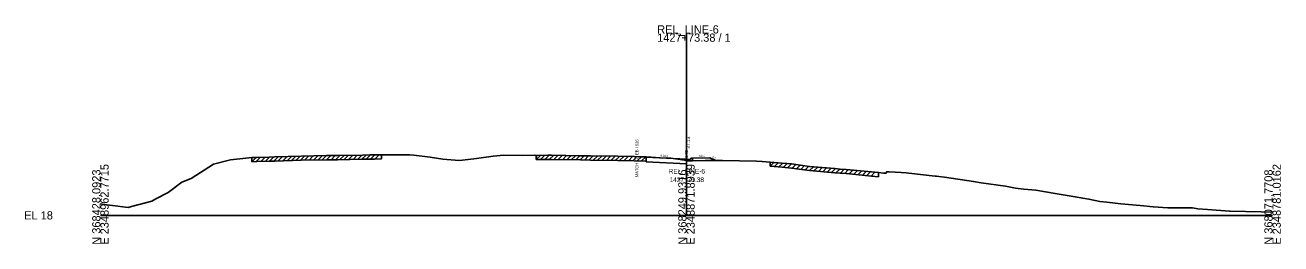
# Model space of a CAD drawing. Extents: x -26 to 403, y -10 to 6565.
# Drawn here: x -25.7 to 402.8, y 6490.3 to 6564.8 of the extents above; entities that cross this region are included whole.
import ezdxf

# ---------------------------------------------------------------- set-up
doc = ezdxf.new("R2010")
doc.units = 0
for name, color, linetype in [('RD_GPK_XS_Cell', 7, 'Continuous'), ('RD_XS_Base', 7, 'Continuous'), ('RD_XS_CurbBase', 7, 'Continuous'), ('RD_XS_CurbFront', 7, 'Continuous'), ('RD_XS_CurbTop', 7, 'Continuous'), ('RD_XS_EarthShd', 7, 'Continuous'), ('RD_XS_ExGround', 7, 'Continuous'), ('RD_XS_ExPaveRet', 7, 'Continuous'), ('RD_XS_Pave', 7, 'Continuous'), ('RD_XS_TieSlope', 7, 'Continuous'), ('RD_XS_TX_Elev_EX', 7, 'Continuous'), ('RD_XS_TX_Elev_PR', 7, 'Continuous'), ('RD_XS_TX_MatchLine', 7, 'Continuous'), ('RD_XS_TX_Slope', 7, 'Continuous'), ('RD_XS_TX_Station', 7, 'Continuous'), ('RD_XS_TX_TOC', 7, 'Continuous')]:
    doc.layers.add(name, color=color, linetype=linetype)

msp = doc.modelspace()

# ---------------------------------------------------------------- linework, layer by layer
at = {"layer": 'RD_GPK_XS_Cell'}
for p, q in [((200, 6500), (200, 6561.91)), ((0, 6500), (200, 6500)), ((200, 6500), (400, 6500))]:
    msp.add_line(p, q, dxfattribs=at)
at = {"layer": 'RD_XS_Base'}
for p, q in [((186.2, 6518.23), (186.2, 6519.94)), ((200, 6517.49), (186.2, 6518.23))]:
    msp.add_line(p, q, dxfattribs=at)
at = {"layer": 'RD_XS_CurbBase'}
for p, q in [((201.5, 6518.52), (200, 6518.61)), ((200, 6517.49), (200, 6518.61)), ((202, 6518.52), (201.5, 6518.52)), ((202, 6519.52), (202, 6518.52))]:
    msp.add_line(p, q, dxfattribs=at)
at = {"layer": 'RD_XS_CurbFront'}
msp.add_line((200, 6518.61), (200, 6519.11), dxfattribs=at)
at = {"layer": 'RD_XS_CurbTop'}
for p, q in [((200, 6519.13), (200, 6519.11)), ((200, 6519.11), (201.42, 6519.02)), ((201.42, 6519.02), (201.5, 6519.52)), ((201.5, 6519.52), (202, 6519.52))]:
    msp.add_line(p, q, dxfattribs=at)
at = {"layer": 'RD_XS_EarthShd'}
msp.add_line((202, 6519.52), (208, 6519.64), dxfattribs=at)
at = {"layer": 'RD_XS_ExGround'}
msp.add_lwpolyline([(0, 6503.95), (1.2, 6503.72), (4.12, 6503.33), (9.49, 6502.72), (10.64, 6503.02), (15.38, 6504.23), (17.59, 6504.8), (18.87, 6505.6), (23.18, 6507.73), (27.82, 6511.29), (31.01, 6512.52), (38.61, 6517.46), (44.41, 6518.91), (49.65, 6519.5), (51.7, 6519.69), (53.33, 6519.73), (57.58, 6519.86), (59.55, 6519.92), (68.55, 6520.18), (77.2, 6520.33), (80.88, 6520.39), (89.43, 6520.52), (91.97, 6520.56), (93.56, 6520.6), (95.94, 6520.64), (99.21, 6520.64), (105.54, 6520.57), (106.95, 6520.5), (112.48, 6519.77), (116.89, 6519.14), (122.41, 6518.64), (123.54, 6518.79), (128.3, 6519.38), (134.03, 6520.15), (137.68, 6520.5), (144.17, 6520.42), (148.03, 6520.44), (148.69, 6520.42), (149.26, 6520.43), (152.68, 6520.46), (153.96, 6520.44), (163.8, 6520.28), (167.29, 6520.23), (176.53, 6520.1), (182.19, 6520.01), (186.2, 6519.94), (187.93, 6519.84), (191.05, 6519.6), (194.69, 6519.45), (198.68, 6518.87), (200, 6518.72), (200.58, 6518.66), (203.08, 6518.53), (206.39, 6518.71), (212.34, 6518.68), (223.84, 6518.5), (225.86, 6518.33), (228.51, 6518.14), (232.7, 6517.81), (235.86, 6517.55), (242.01, 6516.68), (250.6, 6515.92), (252.42, 6515.78), (254.52, 6515.63), (263.15, 6514.81), (265.58, 6514.57), (267.24, 6514.42), (268.06, 6514.34), (268.32, 6514.82), (268.7, 6514.8), (269.15, 6514.77), (273.26, 6514.55), (275.01, 6514.47), (275.92, 6514.42), (284.85, 6513.34), (285.33, 6513.32), (286.07, 6513.23), (288.02, 6512.95), (297.91, 6511.5), (300.53, 6511.11), (308.85, 6509.89), (312.24, 6509.31), (315.1, 6508.87), (319.21, 6508.54), (325.78, 6507.46), (333.29, 6506.16), (334.58, 6506.02), (337.33, 6505.54), (341.08, 6504.74), (343.43, 6504.5), (348.24, 6503.9), (354.82, 6503.36), (359.23, 6502.92), (364.3, 6502.53), (365.99, 6502.55), (367.58, 6502.6), (372.68, 6502.54), (374.55, 6502.24), (377.75, 6502.04), (385.28, 6501.47), (385.58, 6501.45), (396.13, 6501.23), (399.38, 6501.12), (400, 6501.15)], dxfattribs=at)
at = {"layer": 'RD_XS_ExPaveRet'}
for p, q in [((51.7, 6518.25), (53.17, 6519.73)), ((51.7, 6518.25), (51.7, 6519.69)), ((51.7, 6518.25), (53.33, 6518.3)), ((53.2, 6518.29), (54.68, 6519.77)), ((53.33, 6518.3), (57.58, 6518.42)), ((54.7, 6518.34), (56.18, 6519.82)), ((56.2, 6518.38), (57.68, 6519.86)), ((57.58, 6518.42), (59.55, 6518.48)), ((57.7, 6518.42), (59.18, 6519.91)), ((59.2, 6518.47), (60.68, 6519.95)), ((59.55, 6518.48), (68.55, 6518.74)), ((60.7, 6518.51), (62.18, 6519.99)), ((62.2, 6518.56), (63.68, 6520.04)), ((63.7, 6518.6), (65.18, 6520.08)), ((65.2, 6518.64), (66.68, 6520.13)), ((66.7, 6518.69), (68.18, 6520.17)), ((68.2, 6518.73), (69.67, 6520.2)), ((68.55, 6518.74), (77.2, 6518.89)), ((69.7, 6518.76), (71.16, 6520.22)), ((71.2, 6518.79), (72.66, 6520.25)), ((72.7, 6518.81), (74.16, 6520.28)), ((74.2, 6518.84), (75.66, 6520.3)), ((75.7, 6518.87), (77.16, 6520.33)), ((77.2, 6518.89), (78.66, 6520.35)), ((77.2, 6518.89), (80.88, 6518.96)), ((78.7, 6518.92), (80.16, 6520.38)), ((80.2, 6518.94), (81.66, 6520.4)), ((80.88, 6518.96), (89.43, 6519.09)), ((81.7, 6518.97), (83.16, 6520.43)), ((83.2, 6518.99), (84.66, 6520.45)), ((84.7, 6519.01), (86.16, 6520.47)), ((86.2, 6519.04), (87.66, 6520.5)), ((87.7, 6519.06), (89.16, 6520.52)), ((89.2, 6519.08), (90.66, 6520.54)), ((89.43, 6519.09), (91.97, 6519.13)), ((90.7, 6519.11), (92.16, 6520.57)), ((91.97, 6519.13), (93.56, 6519.17)), ((92.2, 6519.13), (93.67, 6520.6)), ((93.56, 6519.17), (95.94, 6519.2)), ((93.7, 6519.17), (95.16, 6520.63)), ((95.94, 6520.64), (95.94, 6519.2)), ((148.69, 6518.98), (150.14, 6520.43)), ((148.69, 6518.98), (148.69, 6520.42)), ((148.69, 6518.98), (149.26, 6518.99)), ((149.26, 6518.99), (152.68, 6519.03)), ((150.19, 6519), (151.64, 6520.45)), ((151.69, 6519.01), (153.13, 6520.46)), ((152.68, 6519.03), (153.96, 6519.01)), ((153.19, 6519.02), (154.6, 6520.43)), ((153.96, 6519.01), (163.8, 6518.85)), ((154.69, 6518.99), (156.1, 6520.41)), ((156.19, 6518.97), (157.6, 6520.38)), ((157.69, 6518.94), (159.1, 6520.36)), ((159.19, 6518.92), (160.6, 6520.33)), ((160.69, 6518.9), (162.1, 6520.31)), ((162.19, 6518.87), (163.6, 6520.29)), ((163.69, 6518.85), (165.11, 6520.26)), ((163.8, 6518.85), (167.29, 6518.8)), ((165.19, 6518.83), (166.61, 6520.24)), ((166.69, 6518.8), (168.11, 6520.22)), ((167.29, 6518.8), (176.53, 6518.67)), ((168.19, 6518.78), (169.61, 6520.2)), ((169.69, 6518.76), (171.11, 6520.18)), ((171.19, 6518.74), (172.61, 6520.16)), ((172.69, 6518.72), (174.11, 6520.14)), ((174.19, 6518.7), (175.61, 6520.12)), ((175.69, 6518.68), (177.11, 6520.09)), ((176.53, 6518.67), (182.19, 6518.58)), ((177.19, 6518.66), (178.6, 6520.07)), ((178.69, 6518.63), (180.1, 6520.05)), ((180.19, 6518.61), (181.6, 6520.02)), ((181.69, 6518.58), (183.1, 6520)), ((182.19, 6518.58), (186.2, 6518.5)), ((183.19, 6518.56), (184.6, 6519.97)), ((184.69, 6518.53), (186.1, 6519.94)), ((186.2, 6519.94), (186.2, 6518.5)), ((228.51, 6516.7), (228.51, 6518.14)), ((228.51, 6516.7), (229.84, 6518.03)), ((228.51, 6516.7), (232.7, 6516.38)), ((230.01, 6516.58), (231.34, 6517.92)), ((231.51, 6516.47), (232.84, 6517.8)), ((232.7, 6516.38), (235.86, 6516.11)), ((233.01, 6516.35), (234.34, 6517.68)), ((234.51, 6516.22), (235.84, 6517.55)), ((235.86, 6516.11), (242.01, 6515.24)), ((236.01, 6516.09), (237.27, 6517.35)), ((237.51, 6515.88), (238.77, 6517.14)), ((239.01, 6515.67), (240.27, 6516.93)), ((240.51, 6515.46), (241.77, 6516.72)), ((242.01, 6515.24), (243.33, 6516.56)), ((242.01, 6515.24), (250.6, 6514.48)), ((243.51, 6515.11), (244.83, 6516.43)), ((245.01, 6514.98), (246.33, 6516.3)), ((246.51, 6514.84), (247.83, 6516.16)), ((248.01, 6514.71), (249.33, 6516.03)), ((249.51, 6514.58), (250.83, 6515.9)), ((250.6, 6514.48), (252.42, 6514.34)), ((251.01, 6514.45), (252.35, 6515.78)), ((252.42, 6514.34), (254.52, 6514.2)), ((252.51, 6514.34), (253.86, 6515.68)), ((254.01, 6514.23), (255.33, 6515.56)), ((254.52, 6514.2), (263.15, 6513.37)), ((255.51, 6514.1), (256.82, 6515.41)), ((257.01, 6513.96), (258.32, 6515.27)), ((258.51, 6513.82), (259.82, 6515.13)), ((260.01, 6513.67), (261.32, 6514.98)), ((261.51, 6513.53), (262.82, 6514.84)), ((263.01, 6513.38), (264.32, 6514.69)), ((265.58, 6514.57), (265.58, 6513.14)), ((263.15, 6513.37), (265.58, 6513.14))]:
    msp.add_line(p, q, dxfattribs=at)
at = {"layer": 'RD_XS_Pave'}
msp.add_line((200, 6519.13), (184.01, 6519.98), dxfattribs=at)
at = {"layer": 'RD_XS_TieSlope'}
msp.add_line((208, 6519.64), (209.9, 6518.69), dxfattribs=at)

# ---------------------------------------------------------------- texts
at = {"layer": 'RD_GPK_XS_Cell'}
for s, p in [('1427+73.38 / 1', (190, 6559.11)), ('REL_LINE-6', (190, 6561.91)), ('EL 18', (-26, 6498.6))]:
    msp.add_text(s, height=2.8, dxfattribs=at).set_placement(p)
for s, p in [('N 368428.0923', (0, 6490)), ('E 2348962.7715', (2.8, 6490)), ('N 368249.9316', (200, 6490)), ('E 2348871.8939', (202.8, 6490)), ('N 368071.7708', (400, 6490)), ('E 2348781.0162', (402.8, 6490))]:
    msp.add_text(s, height=2.8, rotation=90, dxfattribs=at).set_placement(p)
at = {"layer": 'RD_XS_TX_Elev_EX'}
msp.add_text('36.72', height=1, rotation=90, dxfattribs=at).set_placement((200.5, 6518.72))
at = {"layer": 'RD_XS_TX_Elev_PR'}
msp.add_text('37.13', height=1.2, rotation=90, dxfattribs=at).set_placement((201.24, 6522.68))
at = {"layer": 'RD_XS_TX_MatchLine'}
msp.add_text('MATCH TO EB I 526', height=1, rotation=90, dxfattribs=at).set_placement((183.59, 6513))
at = {"layer": 'RD_XS_TX_Slope'}
for s, rotation, p in [('0.053', 356.9433, (191.07, 6519.93)), ('50:1', 1.1458, (204.35, 6519.84)), ('2:1', 333.4349, (208.63, 6519.67))]:
    msp.add_text(s, height=0.75, rotation=rotation, dxfattribs=at).set_placement(p)
at = {"layer": 'RD_XS_TX_Station'}
for s, p in [('REL_LINE-6', (193.92, 6514.23)), ('1427+73.38', (194.23, 6511.33))]:
    msp.add_text(s, height=1.6, dxfattribs=at).set_placement(p)
at = {"layer": 'RD_XS_TX_TOC'}
msp.add_text('TOCRT', height=0.05, dxfattribs=at).set_placement((201.22, 6519.47))

doc.saveas('drawing.dxf')
